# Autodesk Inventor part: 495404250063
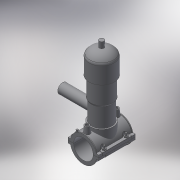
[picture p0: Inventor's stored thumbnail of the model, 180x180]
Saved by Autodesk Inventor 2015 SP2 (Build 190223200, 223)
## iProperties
Created: 2017-07
Part Number: 495404250063
Material: Generic
Description: PLASSON TAPPING VALVE 250-63
Document SubType Name: Modeling
Designer: KIM
Density: 1 g/cm^3
Appearance: Default
Author: KIM
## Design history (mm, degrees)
derived "495404-4954S4.ipt"
feature "Solid1::495404-4954S4.ipt"
feature "Solid2::495404-4954S4.ipt"
tag "TaggingFeature1"
body "Solid1"
body "Solid2"
other parameters: "B_" = 252, "H_" = 186, "L_" = 176, "d_t" = 6, "d_1" = 63, "H_1" = 51, "H_2" = 244, "d148" = 3.75, "d160" = 3.75, "d169" = 3.75, "d192" = 8.5, "d228" = 50.4, "d2" = 327.6, "d3" = 62.5, "d4" = 176, "d5" = 0, "d6" = 0.1, "d8" = 0, "d19" = 6, "d20" = 6, "d21" = 105.6, "d23" = 0, "d24" = 52.8, "d26" = 0, "d27" = 3, "d28" = 3, "d29" = 3, "d30" = 83.33333, "d31" = 6, "d32" = 0, "d33" = 0, "d34" = 0.6, "d40" = 152.1, "d47" = 197.25, "d70" = 15, "d72" = 0, "d73" = 6, "d75" = 5, "d76" = 0, "d77" = 12.5, "d78" = 155, "d79" = 15, "d80" = 70.4, "d82" = 5 deg, "d84" = 4, "d85" = 14, "d86" = 0, "d87" = 3, "d88" = 0, "d89" = 1, "d90" = 1, "d91" = 140.8, "d92" = 0, "d93" = 0.5, "d94" = 131.57895, "d96" = 301.275, "d97" = 3.52, "d98" = 0, "d120" = 140 deg, "d121" = 24.228, "d122" = 20 deg, "d123" = 585, "d124" = 175.5, "d126" = 0, "d143" = 257.5, "d145" = 32.69231, "d149" = 3.75, "d150" = 35.96154, "d153" = 176, "d154" = 0, "d156" = 146.25, "d157" = 160 deg, "d159" = 8.5, "d161" = 3.75, "d162" = 105.6, "d163" = 0, "d164" = 125, "d167" = 25, "d168" = 142.68293, "d170" = 3.75, "d172" = 0, "d173" = 1, "d175" = 125, "d176" = 20 deg, "d177" = 17.5, "d178" = 42.5, "d180" = 0, "d183" = 17, "d184" = 14, "d185" = 57.2, "d186" = 57.2, "d187" = 146.25, "d188" = 12.75, "d189" = 17.5, "d190" = 0, "d191" = 219.375, "d193" = 8.5, "d194" = 4.4, "d195" = 90 deg, "d197" = 0, "d199" = 0, "d205" = 14.64, "d206" = 81.33333, "d207" = 244, "d208" = 224.48, "d209" = 207.4, "d210" = 200.08, "d211" = 146.4, "d212" = 85.4, "d213" = 65.88, "d214" = 73.2, "d216" = 21.96, "d217" = 70.76, "d218" = 80.52, "d222" = 0, "d223" = 292.5, "d224" = 186, "d225" = 51, "d226" = 63, "d229" = 186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
